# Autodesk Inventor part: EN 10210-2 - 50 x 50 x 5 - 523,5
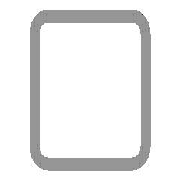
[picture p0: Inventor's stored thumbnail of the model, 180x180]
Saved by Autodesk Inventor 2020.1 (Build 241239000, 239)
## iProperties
_CCFamilyMember: 16
_CCFamilyDisplayName: DIN EN 10210-2 (USAS B17.1 quadratisch) - Rohrleitung — In Klammern angegebene Größen wurden aufgehoben
_FrameMemberDoc: Frame Member File
_Version: 15.0.0
_GetPNFromCC: 1
Created: 2019-01
Part Number: EN 10210-2 - 50 x 50 x 5 - 523,5
Material: Stahl, weich
Description: Rohrleitung
Document SubType Name: Modeling
Standard: DIN
Designer: lutzd
Standard Revision: 2006-07
Standards Organization: DIN
Language: de-DE
Size Designation: 50 x 50 x 5
Categories: <MemberInstance><Categories><Category DisplayName="Profile" InternalName="089c4875-fa83-4c05-b084-43b9cc11f5ed" Mnemonic="GRDR"><CategoryParameter DisplayName="
Stock Number: 50 x 50 x 5
Mass: 3582.84 g
Surface Area: 1791.12 cm^2
Volume: 456.413 cm^3
Density: 7.85 g/cm^3
Appearance: Halbpoliert
G_L: 523,500 mm
G_W: 50,000 mm
G_H: 50,000 mm
DocNumber: ADSK-014080
Folder: .
Dimensions: 50x50x523,5 mm
Mass: 3,583 kg
+36869305-EDDC-4386-8C46-51AF32D5B949+SCHNITTDETAIL1: Schnittwinkel 90,00 grd
IsCustomPart: 1
Title: Profil-Bauteil
Author: lutzd
Revision Number: -
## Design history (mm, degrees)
node "Startebene"
node "Endebene"
sketch "Skizze"
  geometry: L1 (-25, -17.5)-(-25, 17.5); L2 (-17.5, 25)-(17.5, 25); L3 (25, 17.5)-(25, -17.5); L4 (17.5, -25)-(-17.5, -25); L5 (-15, 20)-(15, 20); L6 (20, 15)-(20, -15); L7 (15, -20)-(-15, -20); L8 (-20, -15)-(-20, 15); L9 (0, 37.175)-(0, -37.175) reference; L10 (-37.175, 0)-(37.175, 0) reference; A1 r 7.5 centre (-17.5, -17.5) between (-25, -17.5) and (-17.5, -25); A2 r 7.5 centre (-17.5, 17.5) between (-17.5, 25) and (-25, 17.5); A3 r 7.5 centre (17.5, 17.5) between (25, 17.5) and (17.5, 25); A4 r 7.5 centre (17.5, -17.5) between (17.5, -25) and (25, -17.5); A5 r 5 centre (-15, -15) between (-20, -15) and (-15, -20); A6 r 5 centre (-15, 15) between (-15, 20) and (-20, 15); A7 r 5 centre (15, 15) between (20, 15) and (15, 20); A8 r 5 centre (15, -15) between (15, -20) and (20, -15)
  constraints: 16 end point, 16 point on circle, 16 tangent, 8 centre point, 6 equal radius, 4 parallel, 2 perpendicular, 2 other
  dimensions: "d7" = 7.5 radius of A1 (= G_IR); "d10" = 50 distance between parallel lines of L2 L4 (= G_H); "d11" = 50 distance between parallel lines of L1 L3 (= G_W); "d12" = 5 distance between parallel lines of L3 L6 (= G_T); "d15" = 25 distance between parallel lines of L2 L10 (= 0.5 x d10); "d16" = 25 distance between parallel lines of L9 L3 (= 0.5 x d11); "d19" = 5 radius of A5 (= G_T); "d20" = 5 distance between parallel lines of L4 L7 (= G_T)
extrude "Körper" new body sketch "Skizze" stored distance "d3" = 523.5 (= G_L); taper "d4" = 0 deg
node "Driven Length"
  sketch "Sketch3"
    geometry: L1 (0, 0)-(10, 0) reference
    constraints: 2 end point, 1 horizontal
  workplane "Work Plane3"
  sketch "Sketch4"
    geometry: L1 (-2, 25)-(12, 25) reference; L2 (-2, 548.5)-(12, 548.5) reference
    dimensions: "d18" = 523.5 distance between parallel lines of L1 L2 (derived)
workplane "Arbeitsebene4"
feature "Trennen1"
sketch "Skizze5"
  geometry: L1 (35, 0)-(0, 0) reference; L2 (17.5, 0)-(17.5, 453); 3 further points
  constraints: 2 end point, 1 coincident, 1 midpoint, 1 point on line, 1 vertical
  dimensions: "d21" = 45 distance of point (17.5, 408) point (17.5, 453); "d22" = 408 distance from line of L1 point (17.5, 408)
hole "Bohrung1" sketch "Skizze5" at (17.5, 453), (17.5, 408) diameter "d23" = 6.647; stored, may be unused: countersink angle "d27" = 90 deg, drill point angle "d29" = 118 deg; dims "d24" = 16, "d25" = 4, "d26" = 2, "d28" = 8
sketch "Skizze6"
  geometry: L1 (523.5, 35)-(523.5, 0) reference; L2 (523.5, 17.5)-(202.5, 17.5); 3 further points
  constraints: 2 end point, 1 coincident, 1 horizontal, 1 midpoint, 1 point on line
  dimensions: "d30" = 41 distance of point (243.5, 17.5) point (202.5, 17.5); "d31" = 280 distance from line of L1 point (243.5, 17.5)
hole "Bohrung2" sketch "Skizze6" at (202.5, 17.5), (243.5, 17.5) diameter "d32" = 6.647; stored, may be unused: countersink angle "d36" = 90 deg, drill point angle "d38" = 118 deg; dims "d33" = 16, "d34" = 4, "d35" = 2, "d37" = 8
body "Solid1"
other parameters: "G_W" = 50 [user parameter; used in 1 equation term], "G_H" = 50 [user parameter; used in 1 equation term], "G_T" = 5 [user parameter; used in 3 equation terms], "G_IR" = 7.5 [user parameter; used in 1 equation term], "G_L" = 523.5 (= d18) [user parameter; used in 1 equation term], "G_OFFSET_START" = -25 [user parameter; used in 1 equation term], "G_OFFSET_END" = 63.5 [user parameter; used in 1 equation term], "d13" = 25 (= -G_OFFSET_START), "d14" = 548.5 (= G_OFFSET_END + B_L), "B_L" = 485 [user parameter; used in 1 equation term], "d17" = 90 deg
